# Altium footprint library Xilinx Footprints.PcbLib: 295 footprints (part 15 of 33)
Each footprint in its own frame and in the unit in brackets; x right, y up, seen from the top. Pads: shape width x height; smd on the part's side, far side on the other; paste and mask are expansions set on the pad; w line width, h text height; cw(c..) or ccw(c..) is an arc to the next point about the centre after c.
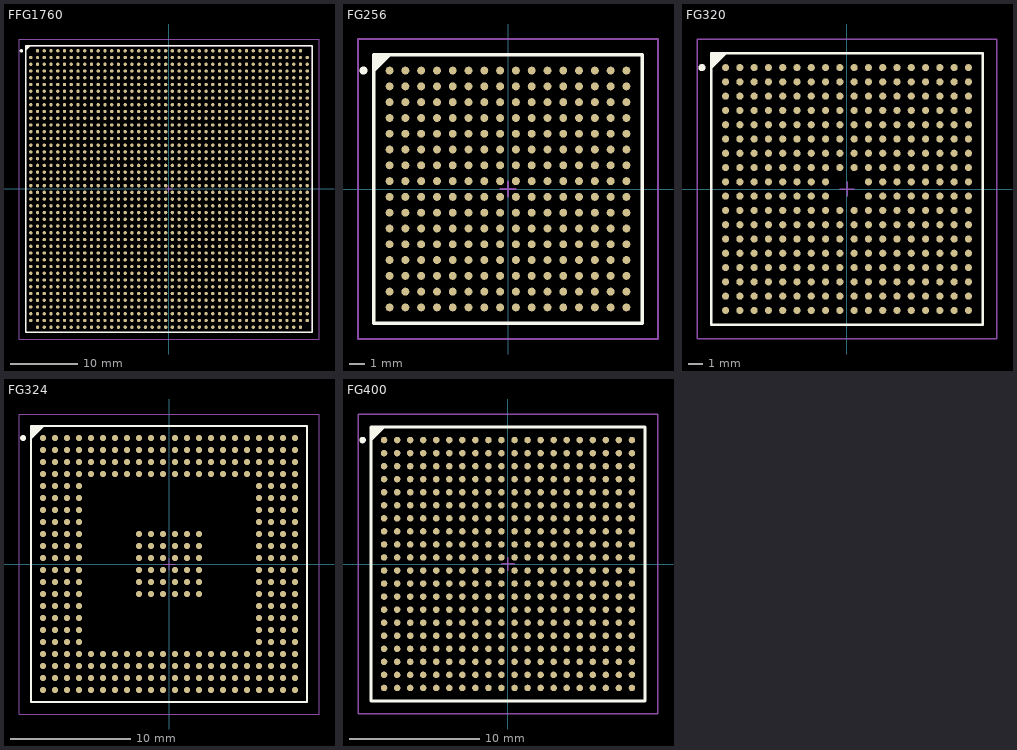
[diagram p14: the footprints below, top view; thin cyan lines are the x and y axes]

## FFG1760 [mm] "1760-Ball Flip Chip Fine Pitch Ball Grid Array (FFG1760) - Pb-Free"
height 3.5
pads (1760):
  round 0.5 smd: A2(-19.5,20.5) A3(-18.5,20.5) A4(-17.5,20.5) A5(-16.5,20.5) A6(-15.5,20.5) A7(-14.5,20.5) A8(-13.5,20.5) A9(-12.5,20.5) A10(-11.5,20.5) A11(-10.5,20.5) A12(-9.5,20.5) A13(-8.5,20.5) A14(-7.5,20.5) A15(-6.5,20.5) A16(-5.5,20.5) A17(-4.5,20.5) A18(-3.5,20.5) A19(-2.5,20.5) A20(-1.5,20.5) A21(-0.5,20.5) A22(0.5,20.5) A23(1.5,20.5) A24(2.5,20.5) A25(3.5,20.5) A26(4.5,20.5) A27(5.5,20.5) A28(6.5,20.5) A29(7.5,20.5) A30(8.5,20.5) A31(9.5,20.5) A32(10.5,20.5) A33(11.5,20.5) A34(12.5,20.5) A35(13.5,20.5) A36(14.5,20.5) A37(15.5,20.5) A38(16.5,20.5) A39(17.5,20.5) A40(18.5,20.5) A41(19.5,20.5) AA1(-20.5,0.5) AA2(-19.5,0.5) AA3(-18.5,0.5) AA4(-17.5,0.5) AA5(-16.5,0.5) AA6(-15.5,0.5) AA7(-14.5,0.5) AA8(-13.5,0.5) AA9(-12.5,0.5) AA10(-11.5,0.5) AA11(-10.5,0.5) AA12(-9.5,0.5) AA13(-8.5,0.5) AA14(-7.5,0.5) AA15(-6.5,0.5) AA16(-5.5,0.5) AA17(-4.5,0.5) AA18(-3.5,0.5) AA19(-2.5,0.5) AA20(-1.5,0.5) AA21(-0.5,0.5) AA22(0.5,0.5) AA23(1.5,0.5) AA24(2.5,0.5) AA25(3.5,0.5) AA26(4.5,0.5) AA27(5.5,0.5) AA28(6.5,0.5) AA29(7.5,0.5) AA30(8.5,0.5) AA31(9.5,0.5) AA32(10.5,0.5) AA33(11.5,0.5) AA34(12.5,0.5) AA35(13.5,0.5) AA36(14.5,0.5) AA37(15.5,0.5) AA38(16.5,0.5) AA39(17.5,0.5) AA40(18.5,0.5) AA41(19.5,0.5) AA42(20.5,0.5) AB1(-20.5,-0.5) AB2(-19.5,-0.5) AB3(-18.5,-0.5) AB4(-17.5,-0.5) AB5(-16.5,-0.5) AB6(-15.5,-0.5) AB7(-14.5,-0.5) AB8(-13.5,-0.5) AB9(-12.5,-0.5) AB10(-11.5,-0.5) AB11(-10.5,-0.5) AB12(-9.5,-0.5) AB13(-8.5,-0.5) AB14(-7.5,-0.5) AB15(-6.5,-0.5) AB16(-5.5,-0.5) AB17(-4.5,-0.5) AB18(-3.5,-0.5) AB19(-2.5,-0.5) AB20(-1.5,-0.5) AB21(-0.5,-0.5) AB22(0.5,-0.5) AB23(1.5,-0.5) AB24(2.5,-0.5) AB25(3.5,-0.5) AB26(4.5,-0.5) AB27(5.5,-0.5) AB28(6.5,-0.5) AB29(7.5,-0.5) AB30(8.5,-0.5) AB31(9.5,-0.5) AB32(10.5,-0.5) AB33(11.5,-0.5) AB34(12.5,-0.5) AB35(13.5,-0.5) AB36(14.5,-0.5) AB37(15.5,-0.5) AB38(16.5,-0.5) AB39(17.5,-0.5) AB40(18.5,-0.5) AB41(19.5,-0.5) AB42(20.5,-0.5) AC1(-20.5,-1.5) AC2(-19.5,-1.5) AC3(-18.5,-1.5) AC4(-17.5,-1.5) AC5(-16.5,-1.5) AC6(-15.5,-1.5) AC7(-14.5,-1.5) AC8(-13.5,-1.5) AC9(-12.5,-1.5) AC10(-11.5,-1.5) AC11(-10.5,-1.5) AC12(-9.5,-1.5) AC13(-8.5,-1.5) AC14(-7.5,-1.5) AC15(-6.5,-1.5) AC16(-5.5,-1.5) AC17(-4.5,-1.5) AC18(-3.5,-1.5) AC19(-2.5,-1.5) AC20(-1.5,-1.5) AC21(-0.5,-1.5) AC22(0.5,-1.5) AC23(1.5,-1.5) AC24(2.5,-1.5) AC25(3.5,-1.5) AC26(4.5,-1.5) AC27(5.5,-1.5) AC28(6.5,-1.5) AC29(7.5,-1.5) AC30(8.5,-1.5) AC31(9.5,-1.5) AC32(10.5,-1.5) AC33(11.5,-1.5) AC34(12.5,-1.5) AC35(13.5,-1.5) AC36(14.5,-1.5) AC37(15.5,-1.5) AC38(16.5,-1.5) AC39(17.5,-1.5) AC40(18.5,-1.5) AC41(19.5,-1.5) AC42(20.5,-1.5) AD1(-20.5,-2.5) AD2(-19.5,-2.5) AD3(-18.5,-2.5) AD4(-17.5,-2.5) AD5(-16.5,-2.5) AD6(-15.5,-2.5) AD7(-14.5,-2.5) AD8(-13.5,-2.5) AD9(-12.5,-2.5) AD10(-11.5,-2.5) AD11(-10.5,-2.5) AD12(-9.5,-2.5) AD13(-8.5,-2.5) AD14(-7.5,-2.5) AD15(-6.5,-2.5) AD16(-5.5,-2.5) AD17(-4.5,-2.5) AD18(-3.5,-2.5) AD19(-2.5,-2.5) AD20(-1.5,-2.5) AD21(-0.5,-2.5) AD22(0.5,-2.5) AD23(1.5,-2.5) AD24(2.5,-2.5) AD25(3.5,-2.5) AD26(4.5,-2.5) AD27(5.5,-2.5) AD28(6.5,-2.5) AD29(7.5,-2.5) AD30(8.5,-2.5) AD31(9.5,-2.5) AD32(10.5,-2.5) AD33(11.5,-2.5) AD34(12.5,-2.5) AD35(13.5,-2.5) AD36(14.5,-2.5) AD37(15.5,-2.5) AD38(16.5,-2.5) AD39(17.5,-2.5) AD40(18.5,-2.5) AD41(19.5,-2.5) AD42(20.5,-2.5) AE1(-20.5,-3.5) AE2(-19.5,-3.5) AE3(-18.5,-3.5) AE4(-17.5,-3.5) AE5(-16.5,-3.5) AE6(-15.5,-3.5) AE7(-14.5,-3.5) AE8(-13.5,-3.5) AE9(-12.5,-3.5) AE10(-11.5,-3.5) AE11(-10.5,-3.5) AE12(-9.5,-3.5) AE13(-8.5,-3.5) AE14(-7.5,-3.5) AE15(-6.5,-3.5) AE16(-5.5,-3.5) AE17(-4.5,-3.5) AE18(-3.5,-3.5) AE19(-2.5,-3.5) AE20(-1.5,-3.5) AE21(-0.5,-3.5) AE22(0.5,-3.5) AE23(1.5,-3.5) AE24(2.5,-3.5) AE25(3.5,-3.5) AE26(4.5,-3.5) AE27(5.5,-3.5) AE28(6.5,-3.5) AE29(7.5,-3.5) AE30(8.5,-3.5) AE31(9.5,-3.5) AE32(10.5,-3.5) AE33(11.5,-3.5) AE34(12.5,-3.5) AE35(13.5,-3.5) AE36(14.5,-3.5) AE37(15.5,-3.5) AE38(16.5,-3.5) AE39(17.5,-3.5) AE40(18.5,-3.5) AE41(19.5,-3.5) AE42(20.5,-3.5) AF1(-20.5,-4.5) AF2(-19.5,-4.5) AF3(-18.5,-4.5) AF4(-17.5,-4.5) AF5(-16.5,-4.5) AF6(-15.5,-4.5) AF7(-14.5,-4.5) AF8(-13.5,-4.5) AF9(-12.5,-4.5) AF10(-11.5,-4.5) AF11(-10.5,-4.5) AF12(-9.5,-4.5) AF13(-8.5,-4.5) AF14(-7.5,-4.5) AF15(-6.5,-4.5) AF16(-5.5,-4.5) AF17(-4.5,-4.5) AF18(-3.5,-4.5) AF19(-2.5,-4.5) AF20(-1.5,-4.5) AF21(-0.5,-4.5) AF22(0.5,-4.5) AF23(1.5,-4.5) AF24(2.5,-4.5) AF25(3.5,-4.5) AF26(4.5,-4.5) AF27(5.5,-4.5) AF28(6.5,-4.5) AF29(7.5,-4.5) AF30(8.5,-4.5) AF31(9.5,-4.5) AF32(10.5,-4.5) AF33(11.5,-4.5) AF34(12.5,-4.5) AF35(13.5,-4.5) AF36(14.5,-4.5) AF37(15.5,-4.5) AF38(16.5,-4.5) AF39(17.5,-4.5) AF40(18.5,-4.5) AF41(19.5,-4.5) AF42(20.5,-4.5) AG1(-20.5,-5.5) AG2(-19.5,-5.5) AG3(-18.5,-5.5) AG4(-17.5,-5.5) AG5(-16.5,-5.5) AG6(-15.5,-5.5) AG7(-14.5,-5.5) AG8(-13.5,-5.5) AG9(-12.5,-5.5) AG10(-11.5,-5.5) AG11(-10.5,-5.5) AG12(-9.5,-5.5) AG13(-8.5,-5.5) AG14(-7.5,-5.5) AG15(-6.5,-5.5) AG16(-5.5,-5.5) AG17(-4.5,-5.5) AG18(-3.5,-5.5) AG19(-2.5,-5.5) AG20(-1.5,-5.5) AG21(-0.5,-5.5) AG22(0.5,-5.5) AG23(1.5,-5.5) AG24(2.5,-5.5) AG25(3.5,-5.5) AG26(4.5,-5.5) AG27(5.5,-5.5) AG28(6.5,-5.5) AG29(7.5,-5.5) AG30(8.5,-5.5) AG31(9.5,-5.5) AG32(10.5,-5.5) AG33(11.5,-5.5) AG34(12.5,-5.5) AG35(13.5,-5.5) AG36(14.5,-5.5) AG37(15.5,-5.5) AG38(16.5,-5.5) AG39(17.5,-5.5) AG40(18.5,-5.5) AG41(19.5,-5.5) AG42(20.5,-5.5) AH1(-20.5,-6.5) AH2(-19.5,-6.5) AH3(-18.5,-6.5) AH4(-17.5,-6.5) AH5(-16.5,-6.5) AH6(-15.5,-6.5) AH7(-14.5,-6.5) AH8(-13.5,-6.5) AH9(-12.5,-6.5) AH10(-11.5,-6.5) AH11(-10.5,-6.5) AH12(-9.5,-6.5) AH13(-8.5,-6.5) AH14(-7.5,-6.5) AH15(-6.5,-6.5) AH16(-5.5,-6.5) AH17(-4.5,-6.5) AH18(-3.5,-6.5) AH19(-2.5,-6.5) AH20(-1.5,-6.5) AH21(-0.5,-6.5) AH22(0.5,-6.5) AH23(1.5,-6.5) AH24(2.5,-6.5) AH25(3.5,-6.5) AH26(4.5,-6.5) AH27(5.5,-6.5) AH28(6.5,-6.5) AH29(7.5,-6.5) AH30(8.5,-6.5) AH31(9.5,-6.5) AH32(10.5,-6.5) AH33(11.5,-6.5) AH34(12.5,-6.5) AH35(13.5,-6.5) AH36(14.5,-6.5) AH37(15.5,-6.5) AH38(16.5,-6.5) AH39(17.5,-6.5) AH40(18.5,-6.5) AH41(19.5,-6.5) AH42(20.5,-6.5) AJ1(-20.5,-7.5) AJ2(-19.5,-7.5) AJ3(-18.5,-7.5) AJ4(-17.5,-7.5) AJ5(-16.5,-7.5) AJ6(-15.5,-7.5) AJ7(-14.5,-7.5) AJ8(-13.5,-7.5) AJ9(-12.5,-7.5) AJ10(-11.5,-7.5) AJ11(-10.5,-7.5) AJ12(-9.5,-7.5) AJ13(-8.5,-7.5) AJ14(-7.5,-7.5) AJ15(-6.5,-7.5) AJ16(-5.5,-7.5) AJ17(-4.5,-7.5) AJ18(-3.5,-7.5) AJ19(-2.5,-7.5) AJ20(-1.5,-7.5) AJ21(-0.5,-7.5) AJ22(0.5,-7.5) AJ23(1.5,-7.5) AJ24(2.5,-7.5) AJ25(3.5,-7.5) AJ26(4.5,-7.5) AJ27(5.5,-7.5) AJ28(6.5,-7.5) AJ29(7.5,-7.5) AJ30(8.5,-7.5) AJ31(9.5,-7.5) AJ32(10.5,-7.5) AJ33(11.5,-7.5) AJ34(12.5,-7.5) AJ35(13.5,-7.5) AJ36(14.5,-7.5) AJ37(15.5,-7.5) AJ38(16.5,-7.5) AJ39(17.5,-7.5) AJ40(18.5,-7.5) AJ41(19.5,-7.5) AJ42(20.5,-7.5) AK1(-20.5,-8.5) AK2(-19.5,-8.5) AK3(-18.5,-8.5) AK4(-17.5,-8.5) AK5(-16.5,-8.5) AK6(-15.5,-8.5) AK7(-14.5,-8.5) AK8(-13.5,-8.5) AK9(-12.5,-8.5) AK10(-11.5,-8.5) AK11(-10.5,-8.5) AK12(-9.5,-8.5) AK13(-8.5,-8.5) AK14(-7.5,-8.5) AK15(-6.5,-8.5) AK16(-5.5,-8.5) AK17(-4.5,-8.5) AK18(-3.5,-8.5) AK19(-2.5,-8.5) AK20(-1.5,-8.5) AK21(-0.5,-8.5) AK22(0.5,-8.5) AK23(1.5,-8.5) AK24(2.5,-8.5) AK25(3.5,-8.5) AK26(4.5,-8.5) AK27(5.5,-8.5) AK28(6.5,-8.5) AK29(7.5,-8.5) AK30(8.5,-8.5) AK31(9.5,-8.5) AK32(10.5,-8.5) AK33(11.5,-8.5) AK34(12.5,-8.5) AK35(13.5,-8.5) AK36(14.5,-8.5) AK37(15.5,-8.5) AK38(16.5,-8.5) AK39(17.5,-8.5) AK40(18.5,-8.5) AK41(19.5,-8.5) AK42(20.5,-8.5) AL1(-20.5,-9.5) AL2(-19.5,-9.5) AL3(-18.5,-9.5) AL4(-17.5,-9.5) AL5(-16.5,-9.5) AL6(-15.5,-9.5) AL7(-14.5,-9.5) AL8(-13.5,-9.5) AL9(-12.5,-9.5) AL10(-11.5,-9.5) AL11(-10.5,-9.5) AL12(-9.5,-9.5) AL13(-8.5,-9.5) AL14(-7.5,-9.5) AL15(-6.5,-9.5) AL16(-5.5,-9.5) AL17(-4.5,-9.5) AL18(-3.5,-9.5) AL19(-2.5,-9.5) AL20(-1.5,-9.5) AL21(-0.5,-9.5) AL22(0.5,-9.5) AL23(1.5,-9.5) AL24(2.5,-9.5) AL25(3.5,-9.5) AL26(4.5,-9.5) AL27(5.5,-9.5) AL28(6.5,-9.5) AL29(7.5,-9.5) AL30(8.5,-9.5) AL31(9.5,-9.5) AL32(10.5,-9.5) AL33(11.5,-9.5) AL34(12.5,-9.5) AL35(13.5,-9.5) AL36(14.5,-9.5) AL37(15.5,-9.5) AL38(16.5,-9.5) AL39(17.5,-9.5) AL40(18.5,-9.5) AL41(19.5,-9.5) AL42(20.5,-9.5) AM1(-20.5,-10.5) AM2(-19.5,-10.5) AM3(-18.5,-10.5) AM4(-17.5,-10.5) AM5(-16.5,-10.5) AM6(-15.5,-10.5) AM7(-14.5,-10.5) AM8(-13.5,-10.5) AM9(-12.5,-10.5) AM10(-11.5,-10.5) AM11(-10.5,-10.5) AM12(-9.5,-10.5) AM13(-8.5,-10.5) AM14(-7.5,-10.5) AM15(-6.5,-10.5) AM16(-5.5,-10.5) AM17(-4.5,-10.5) AM18(-3.5,-10.5) AM19(-2.5,-10.5) AM20(-1.5,-10.5) AM21(-0.5,-10.5) AM22(0.5,-10.5) AM23(1.5,-10.5) AM24(2.5,-10.5) AM25(3.5,-10.5) AM26(4.5,-10.5) AM27(5.5,-10.5) AM28(6.5,-10.5) AM29(7.5,-10.5) AM30(8.5,-10.5) AM31(9.5,-10.5) AM32(10.5,-10.5) AM33(11.5,-10.5) AM34(12.5,-10.5) AM35(13.5,-10.5) AM36(14.5,-10.5) AM37(15.5,-10.5) AM38(16.5,-10.5) AM39(17.5,-10.5) AM40(18.5,-10.5) AM41(19.5,-10.5) AM42(20.5,-10.5) AN1(-20.5,-11.5) AN2(-19.5,-11.5) AN3(-18.5,-11.5) AN4(-17.5,-11.5) AN5(-16.5,-11.5) AN6(-15.5,-11.5) AN7(-14.5,-11.5) AN8(-13.5,-11.5) AN9(-12.5,-11.5) AN10(-11.5,-11.5) AN11(-10.5,-11.5) AN12(-9.5,-11.5) AN13(-8.5,-11.5) AN14(-7.5,-11.5) AN15(-6.5,-11.5) AN16(-5.5,-11.5) AN17(-4.5,-11.5) AN18(-3.5,-11.5) AN19(-2.5,-11.5) AN20(-1.5,-11.5) AN21(-0.5,-11.5) AN22(0.5,-11.5) AN23(1.5,-11.5) AN24(2.5,-11.5) AN25(3.5,-11.5) AN26(4.5,-11.5) AN27(5.5,-11.5) AN28(6.5,-11.5) AN29(7.5,-11.5) AN30(8.5,-11.5) AN31(9.5,-11.5) AN32(10.5,-11.5) AN33(11.5,-11.5) AN34(12.5,-11.5) AN35(13.5,-11.5) AN36(14.5,-11.5) AN37(15.5,-11.5) AN38(16.5,-11.5) AN39(17.5,-11.5) AN40(18.5,-11.5) AN41(19.5,-11.5) AN42(20.5,-11.5) AP1(-20.5,-12.5) AP2(-19.5,-12.5) AP3(-18.5,-12.5) AP4(-17.5,-12.5) AP5(-16.5,-12.5) AP6(-15.5,-12.5) AP7(-14.5,-12.5) AP8(-13.5,-12.5) AP9(-12.5,-12.5) AP10(-11.5,-12.5) AP11(-10.5,-12.5) AP12(-9.5,-12.5) AP13(-8.5,-12.5) AP14(-7.5,-12.5) AP15(-6.5,-12.5) AP16(-5.5,-12.5) AP17(-4.5,-12.5) AP18(-3.5,-12.5) AP19(-2.5,-12.5) AP20(-1.5,-12.5) AP21(-0.5,-12.5) AP22(0.5,-12.5) AP23(1.5,-12.5) AP24(2.5,-12.5) AP25(3.5,-12.5) AP26(4.5,-12.5) AP27(5.5,-12.5) AP28(6.5,-12.5) AP29(7.5,-12.5) AP30(8.5,-12.5) AP31(9.5,-12.5) AP32(10.5,-12.5) AP33(11.5,-12.5) AP34(12.5,-12.5) AP35(13.5,-12.5) AP36(14.5,-12.5) AP37(15.5,-12.5) AP38(16.5,-12.5) AP39(17.5,-12.5) AP40(18.5,-12.5) AP41(19.5,-12.5) AP42(20.5,-12.5) AR1(-20.5,-13.5) AR2(-19.5,-13.5) AR3(-18.5,-13.5) AR4(-17.5,-13.5) AR5(-16.5,-13.5) AR6(-15.5,-13.5) AR7(-14.5,-13.5) AR8(-13.5,-13.5) AR9(-12.5,-13.5) AR10(-11.5,-13.5) AR11(-10.5,-13.5) AR12(-9.5,-13.5) AR13(-8.5,-13.5) AR14(-7.5,-13.5) AR15(-6.5,-13.5) AR16(-5.5,-13.5) AR17(-4.5,-13.5) AR18(-3.5,-13.5) AR19(-2.5,-13.5) AR20(-1.5,-13.5) AR21(-0.5,-13.5) AR22(0.5,-13.5) AR23(1.5,-13.5) AR24(2.5,-13.5) AR25(3.5,-13.5) AR26(4.5,-13.5) AR27(5.5,-13.5) AR28(6.5,-13.5) AR29(7.5,-13.5) AR30(8.5,-13.5) AR31(9.5,-13.5) AR32(10.5,-13.5) AR33(11.5,-13.5) AR34(12.5,-13.5) AR35(13.5,-13.5) AR36(14.5,-13.5) AR37(15.5,-13.5) AR38(16.5,-13.5) AR39(17.5,-13.5) AR40(18.5,-13.5) AR41(19.5,-13.5) AR42(20.5,-13.5) AT1(-20.5,-14.5) AT2(-19.5,-14.5) AT3(-18.5,-14.5) AT4(-17.5,-14.5) AT5(-16.5,-14.5) AT6(-15.5,-14.5) AT7(-14.5,-14.5) AT8(-13.5,-14.5) AT9(-12.5,-14.5) AT10(-11.5,-14.5) AT11(-10.5,-14.5) AT12(-9.5,-14.5) AT13(-8.5,-14.5) AT14(-7.5,-14.5) AT15(-6.5,-14.5) AT16(-5.5,-14.5) AT17(-4.5,-14.5) AT18(-3.5,-14.5) AT19(-2.5,-14.5) AT20(-1.5,-14.5) AT21(-0.5,-14.5) AT22(0.5,-14.5) AT23(1.5,-14.5) AT24(2.5,-14.5) AT25(3.5,-14.5) AT26(4.5,-14.5) AT27(5.5,-14.5) AT28(6.5,-14.5) AT29(7.5,-14.5) AT30(8.5,-14.5) AT31(9.5,-14.5) AT32(10.5,-14.5) AT33(11.5,-14.5) AT34(12.5,-14.5) AT35(13.5,-14.5) AT36(14.5,-14.5) AT37(15.5,-14.5) AT38(16.5,-14.5) AT39(17.5,-14.5) AT40(18.5,-14.5) AT41(19.5,-14.5) AT42(20.5,-14.5) AU1(-20.5,-15.5) AU2(-19.5,-15.5) AU3(-18.5,-15.5) AU4(-17.5,-15.5) AU5(-16.5,-15.5) AU6(-15.5,-15.5) AU7(-14.5,-15.5) AU8(-13.5,-15.5) AU9(-12.5,-15.5) AU10(-11.5,-15.5) AU11(-10.5,-15.5) AU12(-9.5,-15.5) AU13(-8.5,-15.5) AU14(-7.5,-15.5) AU15(-6.5,-15.5) AU16(-5.5,-15.5) AU17(-4.5,-15.5) AU18(-3.5,-15.5) AU19(-2.5,-15.5) AU20(-1.5,-15.5) AU21(-0.5,-15.5) AU22(0.5,-15.5) AU23(1.5,-15.5) AU24(2.5,-15.5) AU25(3.5,-15.5) AU26(4.5,-15.5) AU27(5.5,-15.5) AU28(6.5,-15.5) AU29(7.5,-15.5) AU30(8.5,-15.5) AU31(9.5,-15.5) AU32(10.5,-15.5) AU33(11.5,-15.5) AU34(12.5,-15.5) AU35(13.5,-15.5) AU36(14.5,-15.5) AU37(15.5,-15.5) AU38(16.5,-15.5) AU39(17.5,-15.5) AU40(18.5,-15.5) AU41(19.5,-15.5) AU42(20.5,-15.5) AV1(-20.5,-16.5) AV2(-19.5,-16.5) AV3(-18.5,-16.5) AV4(-17.5,-16.5) AV5(-16.5,-16.5) AV6(-15.5,-16.5) AV7(-14.5,-16.5) AV8(-13.5,-16.5) AV9(-12.5,-16.5) AV10(-11.5,-16.5) AV11(-10.5,-16.5) AV12(-9.5,-16.5) AV13(-8.5,-16.5) AV14(-7.5,-16.5) AV15(-6.5,-16.5) AV16(-5.5,-16.5) AV17(-4.5,-16.5) AV18(-3.5,-16.5) AV19(-2.5,-16.5) AV20(-1.5,-16.5) AV21(-0.5,-16.5) AV22(0.5,-16.5) AV23(1.5,-16.5) AV24(2.5,-16.5) AV25(3.5,-16.5) AV26(4.5,-16.5) AV27(5.5,-16.5) AV28(6.5,-16.5) AV29(7.5,-16.5) AV30(8.5,-16.5) AV31(9.5,-16.5) AV32(10.5,-16.5) AV33(11.5,-16.5) AV34(12.5,-16.5) AV35(13.5,-16.5) AV36(14.5,-16.5) AV37(15.5,-16.5) AV38(16.5,-16.5) AV39(17.5,-16.5) AV40(18.5,-16.5) AV41(19.5,-16.5) AV42(20.5,-16.5) AW1(-20.5,-17.5) AW2(-19.5,-17.5) AW3(-18.5,-17.5) AW4(-17.5,-17.5) AW5(-16.5,-17.5) AW6(-15.5,-17.5) AW7(-14.5,-17.5) AW8(-13.5,-17.5) AW9(-12.5,-17.5) AW10(-11.5,-17.5) AW11(-10.5,-17.5) AW12(-9.5,-17.5) AW13(-8.5,-17.5) AW14(-7.5,-17.5) AW15(-6.5,-17.5) AW16(-5.5,-17.5) AW17(-4.5,-17.5) AW18(-3.5,-17.5) AW19(-2.5,-17.5) AW20(-1.5,-17.5) AW21(-0.5,-17.5) AW22(0.5,-17.5) AW23(1.5,-17.5) AW24(2.5,-17.5) AW25(3.5,-17.5) AW26(4.5,-17.5) AW27(5.5,-17.5) AW28(6.5,-17.5) AW29(7.5,-17.5) AW30(8.5,-17.5) AW31(9.5,-17.5) AW32(10.5,-17.5) AW33(11.5,-17.5) AW34(12.5,-17.5) AW35(13.5,-17.5) AW36(14.5,-17.5) AW37(15.5,-17.5) AW38(16.5,-17.5) AW39(17.5,-17.5) AW40(18.5,-17.5) AW41(19.5,-17.5) AW42(20.5,-17.5) AY1(-20.5,-18.5) AY2(-19.5,-18.5) AY3(-18.5,-18.5) AY4(-17.5,-18.5) AY5(-16.5,-18.5) AY6(-15.5,-18.5) AY7(-14.5,-18.5) AY8(-13.5,-18.5) AY9(-12.5,-18.5) AY10(-11.5,-18.5) AY11(-10.5,-18.5) AY12(-9.5,-18.5) AY13(-8.5,-18.5) AY14(-7.5,-18.5) AY15(-6.5,-18.5) AY16(-5.5,-18.5) AY17(-4.5,-18.5) AY18(-3.5,-18.5) AY19(-2.5,-18.5) AY20(-1.5,-18.5) AY21(-0.5,-18.5) AY22(0.5,-18.5) AY23(1.5,-18.5) AY24(2.5,-18.5) AY25(3.5,-18.5) AY26(4.5,-18.5) AY27(5.5,-18.5) AY28(6.5,-18.5) AY29(7.5,-18.5) AY30(8.5,-18.5) AY31(9.5,-18.5) AY32(10.5,-18.5) AY33(11.5,-18.5) AY34(12.5,-18.5) AY35(13.5,-18.5) AY36(14.5,-18.5) AY37(15.5,-18.5) AY38(16.5,-18.5) AY39(17.5,-18.5) AY40(18.5,-18.5) AY41(19.5,-18.5) AY42(20.5,-18.5) B1(-20.5,19.5) B2(-19.5,19.5) B3(-18.5,19.5) B4(-17.5,19.5) B5(-16.5,19.5) B6(-15.5,19.5) B7(-14.5,19.5) B8(-13.5,19.5) B9(-12.5,19.5) B10(-11.5,19.5) B11(-10.5,19.5) B12(-9.5,19.5) B13(-8.5,19.5) B14(-7.5,19.5) B15(-6.5,19.5) B16(-5.5,19.5) B17(-4.5,19.5) B18(-3.5,19.5) B19(-2.5,19.5) B20(-1.5,19.5) B21(-0.5,19.5) B22(0.5,19.5) B23(1.5,19.5) B24(2.5,19.5) B25(3.5,19.5) B26(4.5,19.5) B27(5.5,19.5) B28(6.5,19.5) B29(7.5,19.5) B30(8.5,19.5) B31(9.5,19.5) B32(10.5,19.5) B33(11.5,19.5) B34(12.5,19.5) B35(13.5,19.5) B36(14.5,19.5) B37(15.5,19.5) B38(16.5,19.5) B39(17.5,19.5) B40(18.5,19.5) B41(19.5,19.5) B42(20.5,19.5) BA1(-20.5,-19.5) BA2(-19.5,-19.5) BA3(-18.5,-19.5) BA4(-17.5,-19.5) BA5(-16.5,-19.5) BA6(-15.5,-19.5) BA7(-14.5,-19.5) BA8(-13.5,-19.5) BA9(-12.5,-19.5) BA10(-11.5,-19.5) BA11(-10.5,-19.5) BA12(-9.5,-19.5) BA13(-8.5,-19.5) BA14(-7.5,-19.5) BA15(-6.5,-19.5) BA16(-5.5,-19.5) BA17(-4.5,-19.5) BA18(-3.5,-19.5) BA19(-2.5,-19.5) BA20(-1.5,-19.5) BA21(-0.5,-19.5) BA22(0.5,-19.5) BA23(1.5,-19.5) BA24(2.5,-19.5) BA25(3.5,-19.5) BA26(4.5,-19.5) BA27(5.5,-19.5) BA28(6.5,-19.5) BA29(7.5,-19.5) BA30(8.5,-19.5) BA31(9.5,-19.5) BA32(10.5,-19.5) BA33(11.5,-19.5) BA34(12.5,-19.5) BA35(13.5,-19.5) BA36(14.5,-19.5) BA37(15.5,-19.5) BA38(16.5,-19.5) BA39(17.5,-19.5) BA40(18.5,-19.5) BA41(19.5,-19.5) BA42(20.5,-19.5) BB2(-19.5,-20.5) BB3(-18.5,-20.5) BB4(-17.5,-20.5) BB5(-16.5,-20.5) BB6(-15.5,-20.5) BB7(-14.5,-20.5) BB8(-13.5,-20.5) BB9(-12.5,-20.5) BB10(-11.5,-20.5) BB11(-10.5,-20.5) BB12(-9.5,-20.5) BB13(-8.5,-20.5) BB14(-7.5,-20.5) BB15(-6.5,-20.5) BB16(-5.5,-20.5) BB17(-4.5,-20.5) BB18(-3.5,-20.5) BB19(-2.5,-20.5) BB20(-1.5,-20.5) BB21(-0.5,-20.5) BB22(0.5,-20.5) BB23(1.5,-20.5) BB24(2.5,-20.5) BB25(3.5,-20.5) BB26(4.5,-20.5) BB27(5.5,-20.5) BB28(6.5,-20.5) BB29(7.5,-20.5) BB30(8.5,-20.5) BB31(9.5,-20.5) BB32(10.5,-20.5) BB33(11.5,-20.5) BB34(12.5,-20.5) BB35(13.5,-20.5) BB36(14.5,-20.5) BB37(15.5,-20.5) BB38(16.5,-20.5) BB39(17.5,-20.5) BB40(18.5,-20.5) BB41(19.5,-20.5) C1(-20.5,18.5) C2(-19.5,18.5) C3(-18.5,18.5) C4(-17.5,18.5) C5(-16.5,18.5) C6(-15.5,18.5) C7(-14.5,18.5) C8(-13.5,18.5) C9(-12.5,18.5) C10(-11.5,18.5) C11(-10.5,18.5) C12(-9.5,18.5) C13(-8.5,18.5) C14(-7.5,18.5) C15(-6.5,18.5) C16(-5.5,18.5) C17(-4.5,18.5) C18(-3.5,18.5) C19(-2.5,18.5) C20(-1.5,18.5) C21(-0.5,18.5) C22(0.5,18.5) C23(1.5,18.5) C24(2.5,18.5) C25(3.5,18.5) C26(4.5,18.5) C27(5.5,18.5) C28(6.5,18.5) C29(7.5,18.5) C30(8.5,18.5) C31(9.5,18.5) C32(10.5,18.5) C33(11.5,18.5) C34(12.5,18.5) C35(13.5,18.5) C36(14.5,18.5) C37(15.5,18.5) C38(16.5,18.5) C39(17.5,18.5) C40(18.5,18.5) C41(19.5,18.5) C42(20.5,18.5) D1(-20.5,17.5) D2(-19.5,17.5) D3(-18.5,17.5) D4(-17.5,17.5) D5(-16.5,17.5) D6(-15.5,17.5) D7(-14.5,17.5) D8(-13.5,17.5) D9(-12.5,17.5) D10(-11.5,17.5) D11(-10.5,17.5) D12(-9.5,17.5) D13(-8.5,17.5) D14(-7.5,17.5) D15(-6.5,17.5) D16(-5.5,17.5) D17(-4.5,17.5) D18(-3.5,17.5) D19(-2.5,17.5) D20(-1.5,17.5) D21(-0.5,17.5) D22(0.5,17.5) D23(1.5,17.5) D24(2.5,17.5) D25(3.5,17.5) D26(4.5,17.5) D27(5.5,17.5) D28(6.5,17.5) D29(7.5,17.5) D30(8.5,17.5) D31(9.5,17.5) D32(10.5,17.5) D33(11.5,17.5) D34(12.5,17.5) D35(13.5,17.5) D36(14.5,17.5) D37(15.5,17.5) D38(16.5,17.5) D39(17.5,17.5) D40(18.5,17.5) D41(19.5,17.5) D42(20.5,17.5) E1(-20.5,16.5) E2(-19.5,16.5) E3(-18.5,16.5) E4(-17.5,16.5) E5(-16.5,16.5) E6(-15.5,16.5) E7(-14.5,16.5) E8(-13.5,16.5) E9(-12.5,16.5) E10(-11.5,16.5) E11(-10.5,16.5) E12(-9.5,16.5) E13(-8.5,16.5) E14(-7.5,16.5) E15(-6.5,16.5) E16(-5.5,16.5) E17(-4.5,16.5) E18(-3.5,16.5) E19(-2.5,16.5) E20(-1.5,16.5) E21(-0.5,16.5) E22(0.5,16.5) E23(1.5,16.5) E24(2.5,16.5) E25(3.5,16.5) E26(4.5,16.5) E27(5.5,16.5) E28(6.5,16.5) E29(7.5,16.5) E30(8.5,16.5) E31(9.5,16.5) E32(10.5,16.5) E33(11.5,16.5) E34(12.5,16.5) E35(13.5,16.5) E36(14.5,16.5) E37(15.5,16.5) E38(16.5,16.5) E39(17.5,16.5) E40(18.5,16.5) E41(19.5,16.5) E42(20.5,16.5) F1(-20.5,15.5) F2(-19.5,15.5) F3(-18.5,15.5) F4(-17.5,15.5) F5(-16.5,15.5) F6(-15.5,15.5) F7(-14.5,15.5) F8(-13.5,15.5) F9(-12.5,15.5) F10(-11.5,15.5) F11(-10.5,15.5) F12(-9.5,15.5) F13(-8.5,15.5) F14(-7.5,15.5) F15(-6.5,15.5) F16(-5.5,15.5) F17(-4.5,15.5) F18(-3.5,15.5) F19(-2.5,15.5) F20(-1.5,15.5) F21(-0.5,15.5) F22(0.5,15.5) F23(1.5,15.5) F24(2.5,15.5) F25(3.5,15.5) F26(4.5,15.5) F27(5.5,15.5) F28(6.5,15.5) F29(7.5,15.5) F30(8.5,15.5) F31(9.5,15.5) F32(10.5,15.5) F33(11.5,15.5) F34(12.5,15.5) F35(13.5,15.5) F36(14.5,15.5) F37(15.5,15.5) F38(16.5,15.5) F39(17.5,15.5) F40(18.5,15.5) F41(19.5,15.5) F42(20.5,15.5) G1(-20.5,14.5) G2(-19.5,14.5) G3(-18.5,14.5) G4(-17.5,14.5) G5(-16.5,14.5) G6(-15.5,14.5) G7(-14.5,14.5) G8(-13.5,14.5) G9(-12.5,14.5) G10(-11.5,14.5) G11(-10.5,14.5) G12(-9.5,14.5) G13(-8.5,14.5) G14(-7.5,14.5) G15(-6.5,14.5) G16(-5.5,14.5) G17(-4.5,14.5) G18(-3.5,14.5) G19(-2.5,14.5) G20(-1.5,14.5) G21(-0.5,14.5) G22(0.5,14.5) G23(1.5,14.5) G24(2.5,14.5) G25(3.5,14.5) G26(4.5,14.5) G27(5.5,14.5) G28(6.5,14.5) G29(7.5,14.5) G30(8.5,14.5) G31(9.5,14.5) G32(10.5,14.5) G33(11.5,14.5) G34(12.5,14.5) G35(13.5,14.5) G36(14.5,14.5) G37(15.5,14.5) G38(16.5,14.5) G39(17.5,14.5) G40(18.5,14.5) G41(19.5,14.5) G42(20.5,14.5) H1(-20.5,13.5) H2(-19.5,13.5) H3(-18.5,13.5) H4(-17.5,13.5) H5(-16.5,13.5) H6(-15.5,13.5) H7(-14.5,13.5) H8(-13.5,13.5) H9(-12.5,13.5) H10(-11.5,13.5) H11(-10.5,13.5) H12(-9.5,13.5) H13(-8.5,13.5) H14(-7.5,13.5) H15(-6.5,13.5) H16(-5.5,13.5) H17(-4.5,13.5) H18(-3.5,13.5) H19(-2.5,13.5) H20(-1.5,13.5) H21(-0.5,13.5) H22(0.5,13.5) H23(1.5,13.5) H24(2.5,13.5) H25(3.5,13.5) H26(4.5,13.5) H27(5.5,13.5) H28(6.5,13.5) H29(7.5,13.5) H30(8.5,13.5) H31(9.5,13.5) H32(10.5,13.5) H33(11.5,13.5) H34(12.5,13.5) H35(13.5,13.5) H36(14.5,13.5) H37(15.5,13.5) H38(16.5,13.5) H39(17.5,13.5) H40(18.5,13.5) H41(19.5,13.5) H42(20.5,13.5) J1(-20.5,12.5) J2(-19.5,12.5) J3(-18.5,12.5) J4(-17.5,12.5) J5(-16.5,12.5) J6(-15.5,12.5) J7(-14.5,12.5) J8(-13.5,12.5) J9(-12.5,12.5) J10(-11.5,12.5) J11(-10.5,12.5) J12(-9.5,12.5) J13(-8.5,12.5) J14(-7.5,12.5) J15(-6.5,12.5) J16(-5.5,12.5) J17(-4.5,12.5) J18(-3.5,12.5) J19(-2.5,12.5) J20(-1.5,12.5) J21(-0.5,12.5) J22(0.5,12.5) J23(1.5,12.5) J24(2.5,12.5) J25(3.5,12.5) J26(4.5,12.5) J27(5.5,12.5) J28(6.5,12.5) J29(7.5,12.5) J30(8.5,12.5) J31(9.5,12.5) J32(10.5,12.5) J33(11.5,12.5) J34(12.5,12.5) J35(13.5,12.5) J36(14.5,12.5) J37(15.5,12.5) J38(16.5,12.5) J39(17.5,12.5) J40(18.5,12.5) J41(19.5,12.5) J42(20.5,12.5) K1(-20.5,11.5) K2(-19.5,11.5) K3(-18.5,11.5) K4(-17.5,11.5) K5(-16.5,11.5) K6(-15.5,11.5) K7(-14.5,11.5) K8(-13.5,11.5) K9(-12.5,11.5) K10(-11.5,11.5) K11(-10.5,11.5) K12(-9.5,11.5) K13(-8.5,11.5) K14(-7.5,11.5) K15(-6.5,11.5) K16(-5.5,11.5) K17(-4.5,11.5) K18(-3.5,11.5) K19(-2.5,11.5) K20(-1.5,11.5) K21(-0.5,11.5) K22(0.5,11.5) K23(1.5,11.5) K24(2.5,11.5) K25(3.5,11.5) K26(4.5,11.5) K27(5.5,11.5) K28(6.5,11.5) K29(7.5,11.5) K30(8.5,11.5) K31(9.5,11.5) K32(10.5,11.5) K33(11.5,11.5) K34(12.5,11.5) K35(13.5,11.5) K36(14.5,11.5) K37(15.5,11.5) K38(16.5,11.5) K39(17.5,11.5) K40(18.5,11.5) K41(19.5,11.5) K42(20.5,11.5) L1(-20.5,10.5) L2(-19.5,10.5) L3(-18.5,10.5) L4(-17.5,10.5) L5(-16.5,10.5) L6(-15.5,10.5) L7(-14.5,10.5) L8(-13.5,10.5) L9(-12.5,10.5) L10(-11.5,10.5) L11(-10.5,10.5) L12(-9.5,10.5) L13(-8.5,10.5) L14(-7.5,10.5) L15(-6.5,10.5) L16(-5.5,10.5) L17(-4.5,10.5) L18(-3.5,10.5) L19(-2.5,10.5) L20(-1.5,10.5) L21(-0.5,10.5) L22(0.5,10.5) L23(1.5,10.5) L24(2.5,10.5) L25(3.5,10.5) L26(4.5,10.5) L27(5.5,10.5) L28(6.5,10.5) L29(7.5,10.5) L30(8.5,10.5) L31(9.5,10.5) L32(10.5,10.5) L33(11.5,10.5) L34(12.5,10.5) L35(13.5,10.5) L36(14.5,10.5) L37(15.5,10.5) L38(16.5,10.5) L39(17.5,10.5) L40(18.5,10.5) L41(19.5,10.5) L42(20.5,10.5) M1(-20.5,9.5) M2(-19.5,9.5) M3(-18.5,9.5) M4(-17.5,9.5) M5(-16.5,9.5) M6(-15.5,9.5) M7(-14.5,9.5) M8(-13.5,9.5) M9(-12.5,9.5) M10(-11.5,9.5) M11(-10.5,9.5) M12(-9.5,9.5) M13(-8.5,9.5) M14(-7.5,9.5) M15(-6.5,9.5) M16(-5.5,9.5) M17(-4.5,9.5) M18(-3.5,9.5) M19(-2.5,9.5) M20(-1.5,9.5) M21(-0.5,9.5) M22(0.5,9.5) M23(1.5,9.5) M24(2.5,9.5) M25(3.5,9.5) M26(4.5,9.5) M27(5.5,9.5) M28(6.5,9.5) M29(7.5,9.5) M30(8.5,9.5) M31(9.5,9.5) M32(10.5,9.5) M33(11.5,9.5) M34(12.5,9.5) M35(13.5,9.5) M36(14.5,9.5) M37(15.5,9.5) M38(16.5,9.5) M39(17.5,9.5) M40(18.5,9.5) M41(19.5,9.5) M42(20.5,9.5) N1(-20.5,8.5) N2(-19.5,8.5) N3(-18.5,8.5) N4(-17.5,8.5) N5(-16.5,8.5) N6(-15.5,8.5) N7(-14.5,8.5) N8(-13.5,8.5) N9(-12.5,8.5) N10(-11.5,8.5) N11(-10.5,8.5) N12(-9.5,8.5) N13(-8.5,8.5) N14(-7.5,8.5) N15(-6.5,8.5) N16(-5.5,8.5) N17(-4.5,8.5) N18(-3.5,8.5) N19(-2.5,8.5) N20(-1.5,8.5) N21(-0.5,8.5) N22(0.5,8.5) N23(1.5,8.5) N24(2.5,8.5) N25(3.5,8.5) N26(4.5,8.5) N27(5.5,8.5) N28(6.5,8.5) N29(7.5,8.5) N30(8.5,8.5) N31(9.5,8.5) N32(10.5,8.5) N33(11.5,8.5) N34(12.5,8.5) N35(13.5,8.5) N36(14.5,8.5) N37(15.5,8.5) N38(16.5,8.5) N39(17.5,8.5) N40(18.5,8.5) N41(19.5,8.5) N42(20.5,8.5) P1(-20.5,7.5) P2(-19.5,7.5) P3(-18.5,7.5) P4(-17.5,7.5) P5(-16.5,7.5) P6(-15.5,7.5) P7(-14.5,7.5) P8(-13.5,7.5) P9(-12.5,7.5) P10(-11.5,7.5) P11(-10.5,7.5) P12(-9.5,7.5) P13(-8.5,7.5) P14(-7.5,7.5) P15(-6.5,7.5) P16(-5.5,7.5) P17(-4.5,7.5) P18(-3.5,7.5) P19(-2.5,7.5) P20(-1.5,7.5) P21(-0.5,7.5) P22(0.5,7.5) P23(1.5,7.5) P24(2.5,7.5) P25(3.5,7.5) P26(4.5,7.5) P27(5.5,7.5) P28(6.5,7.5) P29(7.5,7.5) P30(8.5,7.5) P31(9.5,7.5) P32(10.5,7.5) P33(11.5,7.5) P34(12.5,7.5) P35(13.5,7.5) P36(14.5,7.5) P37(15.5,7.5) P38(16.5,7.5) P39(17.5,7.5) P40(18.5,7.5) P41(19.5,7.5) P42(20.5,7.5) R1(-20.5,6.5) R2(-19.5,6.5) R3(-18.5,6.5) R4(-17.5,6.5) R5(-16.5,6.5) R6(-15.5,6.5) R7(-14.5,6.5) R8(-13.5,6.5) R9(-12.5,6.5) R10(-11.5,6.5) R11(-10.5,6.5) R12(-9.5,6.5) R13(-8.5,6.5) R14(-7.5,6.5) R15(-6.5,6.5) R16(-5.5,6.5) R17(-4.5,6.5) R18(-3.5,6.5) R19(-2.5,6.5) R20(-1.5,6.5) R21(-0.5,6.5) R22(0.5,6.5) R23(1.5,6.5) R24(2.5,6.5) R25(3.5,6.5) R26(4.5,6.5) R27(5.5,6.5) R28(6.5,6.5) R29(7.5,6.5) R30(8.5,6.5) R31(9.5,6.5) R32(10.5,6.5) R33(11.5,6.5) R34(12.5,6.5) R35(13.5,6.5) R36(14.5,6.5) R37(15.5,6.5) R38(16.5,6.5) R39(17.5,6.5) R40(18.5,6.5) R41(19.5,6.5) R42(20.5,6.5) T1(-20.5,5.5) T2(-19.5,5.5) T3(-18.5,5.5) T4(-17.5,5.5) T5(-16.5,5.5) T6(-15.5,5.5) T7(-14.5,5.5) T8(-13.5,5.5) T9(-12.5,5.5) T10(-11.5,5.5) T11(-10.5,5.5) T12(-9.5,5.5) T13(-8.5,5.5) T14(-7.5,5.5) T15(-6.5,5.5) T16(-5.5,5.5) T17(-4.5,5.5) T18(-3.5,5.5) T19(-2.5,5.5) T20(-1.5,5.5) T21(-0.5,5.5) T22(0.5,5.5) T23(1.5,5.5) T24(2.5,5.5) T25(3.5,5.5) T26(4.5,5.5) T27(5.5,5.5) T28(6.5,5.5) T29(7.5,5.5) T30(8.5,5.5) T31(9.5,5.5) T32(10.5,5.5) T33(11.5,5.5) T34(12.5,5.5) T35(13.5,5.5) T36(14.5,5.5) T37(15.5,5.5) T38(16.5,5.5) T39(17.5,5.5) T40(18.5,5.5) T41(19.5,5.5) T42(20.5,5.5) U1(-20.5,4.5) U2(-19.5,4.5) U3(-18.5,4.5) U4(-17.5,4.5) U5(-16.5,4.5) U6(-15.5,4.5) U7(-14.5,4.5) U8(-13.5,4.5) U9(-12.5,4.5) U10(-11.5,4.5) U11(-10.5,4.5) U12(-9.5,4.5) U13(-8.5,4.5) U14(-7.5,4.5) U15(-6.5,4.5) U16(-5.5,4.5) U17(-4.5,4.5) U18(-3.5,4.5) U19(-2.5,4.5) U20(-1.5,4.5) U21(-0.5,4.5) U22(0.5,4.5) U23(1.5,4.5) U24(2.5,4.5) U25(3.5,4.5) U26(4.5,4.5) U27(5.5,4.5) U28(6.5,4.5) U29(7.5,4.5) U30(8.5,4.5) U31(9.5,4.5) U32(10.5,4.5) U33(11.5,4.5) U34(12.5,4.5) U35(13.5,4.5) U36(14.5,4.5) U37(15.5,4.5) U38(16.5,4.5) U39(17.5,4.5) U40(18.5,4.5) U41(19.5,4.5) U42(20.5,4.5) V1(-20.5,3.5) V2(-19.5,3.5) V3(-18.5,3.5) V4(-17.5,3.5) V5(-16.5,3.5) V6(-15.5,3.5) V7(-14.5,3.5) V8(-13.5,3.5) V9(-12.5,3.5) V10(-11.5,3.5) V11(-10.5,3.5) V12(-9.5,3.5) V13(-8.5,3.5) V14(-7.5,3.5) V15(-6.5,3.5) V16(-5.5,3.5) V17(-4.5,3.5) V18(-3.5,3.5) V19(-2.5,3.5) V20(-1.5,3.5) V21(-0.5,3.5) V22(0.5,3.5) V23(1.5,3.5) V24(2.5,3.5) V25(3.5,3.5) V26(4.5,3.5) V27(5.5,3.5) V28(6.5,3.5) V29(7.5,3.5) V30(8.5,3.5) V31(9.5,3.5) V32(10.5,3.5) V33(11.5,3.5) V34(12.5,3.5) V35(13.5,3.5) V36(14.5,3.5) V37(15.5,3.5) V38(16.5,3.5) V39(17.5,3.5) V40(18.5,3.5) V41(19.5,3.5) V42(20.5,3.5) W1(-20.5,2.5) W2(-19.5,2.5) W3(-18.5,2.5) W4(-17.5,2.5) W5(-16.5,2.5) W6(-15.5,2.5) W7(-14.5,2.5) W8(-13.5,2.5) W9(-12.5,2.5) W10(-11.5,2.5) W11(-10.5,2.5) W12(-9.5,2.5) W13(-8.5,2.5) W14(-7.5,2.5) W15(-6.5,2.5) W16(-5.5,2.5) W17(-4.5,2.5) W18(-3.5,2.5) W19(-2.5,2.5) W20(-1.5,2.5) W21(-0.5,2.5) W22(0.5,2.5) W23(1.5,2.5) W24(2.5,2.5) W25(3.5,2.5) W26(4.5,2.5) W27(5.5,2.5) W28(6.5,2.5) W29(7.5,2.5) W30(8.5,2.5) W31(9.5,2.5) W32(10.5,2.5) W33(11.5,2.5) W34(12.5,2.5) W35(13.5,2.5) W36(14.5,2.5) W37(15.5,2.5) W38(16.5,2.5) W39(17.5,2.5) W40(18.5,2.5) W41(19.5,2.5) W42(20.5,2.5) Y1(-20.5,1.5) Y2(-19.5,1.5) Y3(-18.5,1.5) Y4(-17.5,1.5) Y5(-16.5,1.5) Y6(-15.5,1.5) Y7(-14.5,1.5) Y8(-13.5,1.5) Y9(-12.5,1.5) Y10(-11.5,1.5) Y11(-10.5,1.5) Y12(-9.5,1.5) Y13(-8.5,1.5) Y14(-7.5,1.5) Y15(-6.5,1.5) Y16(-5.5,1.5) Y17(-4.5,1.5) Y18(-3.5,1.5) Y19(-2.5,1.5) Y20(-1.5,1.5) Y21(-0.5,1.5) Y22(0.5,1.5) Y23(1.5,1.5) Y24(2.5,1.5) Y25(3.5,1.5) Y26(4.5,1.5) Y27(5.5,1.5) Y28(6.5,1.5) Y29(7.5,1.5) Y30(8.5,1.5) Y31(9.5,1.5) Y32(10.5,1.5) Y33(11.5,1.5) Y34(12.5,1.5) Y35(13.5,1.5) Y36(14.5,1.5) Y37(15.5,1.5) Y38(16.5,1.5) Y39(17.5,1.5) Y40(18.5,1.5) Y41(19.5,1.5) Y42(20.5,1.5)
Top Overlay:
  circle w0.25: c-21.9,20.5 r0.125
  region: -20.669,21.25 -21.25,20.669 -21.25,21.25
  lines w0.2: -21.25,20.669 -20.669,21.25 ; -21.25,-21.25 21.25,-21.25 21.25,21.25 -21.25,21.25 -21.25,-21.25
Mechanical 13:
  lines w0.1: -21.25,-21.25 21.25,-21.25 21.25,21.25 -21.25,21.25 -21.25,-21.25
Mechanical 15:
  lines w0.1: -0.5,0 0.5,0 ; 0,-0.5 0,0.5 ; -22.25,-22.25 22.25,-22.25 22.25,22.25 -22.25,22.25 -22.25,-22.25
3D body: height 3.5, standoff 0, extent -21.25,-21.25 21.25,21.25

## FG256 [mm] "256-Ball Fine Pitch Ball Grid Array (FG256)"
height 2
pads (256):
  round 0.5 smd: A1(-7.5,7.5) A2(-6.5,7.5) A3(-5.5,7.5) A4(-4.5,7.5) A5(-3.5,7.5) A6(-2.5,7.5) A7(-1.5,7.5) A8(-0.5,7.5) A9(0.5,7.5) A10(1.5,7.5) A11(2.5,7.5) A12(3.5,7.5) A13(4.5,7.5) A14(5.5,7.5) A15(6.5,7.5) A16(7.5,7.5) B1(-7.5,6.5) B2(-6.5,6.5) B3(-5.5,6.5) B4(-4.5,6.5) B5(-3.5,6.5) B6(-2.5,6.5) B7(-1.5,6.5) B8(-0.5,6.5) B9(0.5,6.5) B10(1.5,6.5) B11(2.5,6.5) B12(3.5,6.5) B13(4.5,6.5) B14(5.5,6.5) B15(6.5,6.5) B16(7.5,6.5) C1(-7.5,5.5) C2(-6.5,5.5) C3(-5.5,5.5) C4(-4.5,5.5) C5(-3.5,5.5) C6(-2.5,5.5) C7(-1.5,5.5) C8(-0.5,5.5) C9(0.5,5.5) C10(1.5,5.5) C11(2.5,5.5) C12(3.5,5.5) C13(4.5,5.5) C14(5.5,5.5) C15(6.5,5.5) C16(7.5,5.5) D1(-7.5,4.5) D2(-6.5,4.5) D3(-5.5,4.5) D4(-4.5,4.5) D5(-3.5,4.5) D6(-2.5,4.5) D7(-1.5,4.5) D8(-0.5,4.5) D9(0.5,4.5) D10(1.5,4.5) D11(2.5,4.5) D12(3.5,4.5) D13(4.5,4.5) D14(5.5,4.5) D15(6.5,4.5) D16(7.5,4.5) E1(-7.5,3.5) E2(-6.5,3.5) E3(-5.5,3.5) E4(-4.5,3.5) E5(-3.5,3.5) E6(-2.5,3.5) E7(-1.5,3.5) E8(-0.5,3.5) E9(0.5,3.5) E10(1.5,3.5) E11(2.5,3.5) E12(3.5,3.5) E13(4.5,3.5) E14(5.5,3.5) E15(6.5,3.5) E16(7.5,3.5) F1(-7.5,2.5) F2(-6.5,2.5) F3(-5.5,2.5) F4(-4.5,2.5) F5(-3.5,2.5) F6(-2.5,2.5) F7(-1.5,2.5) F8(-0.5,2.5) F9(0.5,2.5) F10(1.5,2.5) F11(2.5,2.5) F12(3.5,2.5) F13(4.5,2.5) F14(5.5,2.5) F15(6.5,2.5) F16(7.5,2.5) G1(-7.5,1.5) G2(-6.5,1.5) G3(-5.5,1.5) G4(-4.5,1.5) G5(-3.5,1.5) G6(-2.5,1.5) G7(-1.5,1.5) G8(-0.5,1.5) G9(0.5,1.5) G10(1.5,1.5) G11(2.5,1.5) G12(3.5,1.5) G13(4.5,1.5) G14(5.5,1.5) G15(6.5,1.5) G16(7.5,1.5) H1(-7.5,0.5) H2(-6.5,0.5) H3(-5.5,0.5) H4(-4.5,0.5) H5(-3.5,0.5) H6(-2.5,0.5) H7(-1.5,0.5) H8(-0.5,0.5) H9(0.5,0.5) H10(1.5,0.5) H11(2.5,0.5) H12(3.5,0.5) H13(4.5,0.5) H14(5.5,0.5) H15(6.5,0.5) H16(7.5,0.5) J1(-7.5,-0.5) J2(-6.5,-0.5) J3(-5.5,-0.5) J4(-4.5,-0.5) J5(-3.5,-0.5) J6(-2.5,-0.5) J7(-1.5,-0.5) J8(-0.5,-0.5) J9(0.5,-0.5) J10(1.5,-0.5) J11(2.5,-0.5) J12(3.5,-0.5) J13(4.5,-0.5) J14(5.5,-0.5) J15(6.5,-0.5) J16(7.5,-0.5) K1(-7.5,-1.5) K2(-6.5,-1.5) K3(-5.5,-1.5) K4(-4.5,-1.5) K5(-3.5,-1.5) K6(-2.5,-1.5) K7(-1.5,-1.5) K8(-0.5,-1.5) K9(0.5,-1.5) K10(1.5,-1.5) K11(2.5,-1.5) K12(3.5,-1.5) K13(4.5,-1.5) K14(5.5,-1.5) K15(6.5,-1.5) K16(7.5,-1.5) L1(-7.5,-2.5) L2(-6.5,-2.5) L3(-5.5,-2.5) L4(-4.5,-2.5) L5(-3.5,-2.5) L6(-2.5,-2.5) L7(-1.5,-2.5) L8(-0.5,-2.5) L9(0.5,-2.5) L10(1.5,-2.5) L11(2.5,-2.5) L12(3.5,-2.5) L13(4.5,-2.5) L14(5.5,-2.5) L15(6.5,-2.5) L16(7.5,-2.5) M1(-7.5,-3.5) M2(-6.5,-3.5) M3(-5.5,-3.5) M4(-4.5,-3.5) M5(-3.5,-3.5) M6(-2.5,-3.5) M7(-1.5,-3.5) M8(-0.5,-3.5) M9(0.5,-3.5) M10(1.5,-3.5) M11(2.5,-3.5) M12(3.5,-3.5) M13(4.5,-3.5) M14(5.5,-3.5) M15(6.5,-3.5) M16(7.5,-3.5) N1(-7.5,-4.5) N2(-6.5,-4.5) N3(-5.5,-4.5) N4(-4.5,-4.5) N5(-3.5,-4.5) N6(-2.5,-4.5) N7(-1.5,-4.5) N8(-0.5,-4.5) N9(0.5,-4.5) N10(1.5,-4.5) N11(2.5,-4.5) N12(3.5,-4.5) N13(4.5,-4.5) N14(5.5,-4.5) N15(6.5,-4.5) N16(7.5,-4.5) P1(-7.5,-5.5) P2(-6.5,-5.5) P3(-5.5,-5.5) P4(-4.5,-5.5) P5(-3.5,-5.5) P6(-2.5,-5.5) P7(-1.5,-5.5) P8(-0.5,-5.5) P9(0.5,-5.5) P10(1.5,-5.5) P11(2.5,-5.5) P12(3.5,-5.5) P13(4.5,-5.5) P14(5.5,-5.5) P15(6.5,-5.5) P16(7.5,-5.5) R1(-7.5,-6.5) R2(-6.5,-6.5) R3(-5.5,-6.5) R4(-4.5,-6.5) R5(-3.5,-6.5) R6(-2.5,-6.5) R7(-1.5,-6.5) R8(-0.5,-6.5) R9(0.5,-6.5) R10(1.5,-6.5) R11(2.5,-6.5) R12(3.5,-6.5) R13(4.5,-6.5) R14(5.5,-6.5) R15(6.5,-6.5) R16(7.5,-6.5) T1(-7.5,-7.5) T2(-6.5,-7.5) T3(-5.5,-7.5) T4(-4.5,-7.5) T5(-3.5,-7.5) T6(-2.5,-7.5) T7(-1.5,-7.5) T8(-0.5,-7.5) T9(0.5,-7.5) T10(1.5,-7.5) T11(2.5,-7.5) T12(3.5,-7.5) T13(4.5,-7.5) T14(5.5,-7.5) T15(6.5,-7.5) T16(7.5,-7.5)
Top Overlay:
  circle w0.25: c-9.15,7.5 r0.125
  region: -7.5,8.5 -8.5,7.5 -8.5,8.5
  lines w0.2: -8.5,7.5 -7.5,8.5 ; -8.5,-8.5 -8.5,8.5 8.5,8.5 8.5,-8.5 -8.5,-8.5
Mechanical 13:
  lines w0.1: -8.5,-8.5 -8.5,8.5 8.5,8.5 8.5,-8.5 -8.5,-8.5
Mechanical 15:
  lines w0.1: -0.5,0 0.5,0 ; 0,-0.5 0,0.5 ; -9.5,-9.5 -9.5,9.5 9.5,9.5 9.5,-9.5 -9.5,-9.5
3D body: height 2, standoff 0, extent -8.5,-8.5 8.5,8.5

## FG320 [mm] "320-Ball Fine Pitch Ball Grid Array (FG320)"
height 2
pads (320):
  round 0.5 smd: A1(-8.5,8.5) A2(-7.5,8.5) A3(-6.5,8.5) A4(-5.5,8.5) A5(-4.5,8.5) A6(-3.5,8.5) A7(-2.5,8.5) A8(-1.5,8.5) A9(-0.5,8.5) A10(0.5,8.5) A11(1.5,8.5) A12(2.5,8.5) A13(3.5,8.5) A14(4.5,8.5) A15(5.5,8.5) A16(6.5,8.5) A17(7.5,8.5) A18(8.5,8.5) B1(-8.5,7.5) B2(-7.5,7.5) B3(-6.5,7.5) B4(-5.5,7.5) B5(-4.5,7.5) B6(-3.5,7.5) B7(-2.5,7.5) B8(-1.5,7.5) B9(-0.5,7.5) B10(0.5,7.5) B11(1.5,7.5) B12(2.5,7.5) B13(3.5,7.5) B14(4.5,7.5) B15(5.5,7.5) B16(6.5,7.5) B17(7.5,7.5) B18(8.5,7.5) C1(-8.5,6.5) C2(-7.5,6.5) C3(-6.5,6.5) C4(-5.5,6.5) C5(-4.5,6.5) C6(-3.5,6.5) C7(-2.5,6.5) C8(-1.5,6.5) C9(-0.5,6.5) C10(0.5,6.5) C11(1.5,6.5) C12(2.5,6.5) C13(3.5,6.5) C14(4.5,6.5) C15(5.5,6.5) C16(6.5,6.5) C17(7.5,6.5) C18(8.5,6.5) D1(-8.5,5.5) D2(-7.5,5.5) D3(-6.5,5.5) D4(-5.5,5.5) D5(-4.5,5.5) D6(-3.5,5.5) D7(-2.5,5.5) D8(-1.5,5.5) D9(-0.5,5.5) D10(0.5,5.5) D11(1.5,5.5) D12(2.5,5.5) D13(3.5,5.5) D14(4.5,5.5) D15(5.5,5.5) D16(6.5,5.5) D17(7.5,5.5) D18(8.5,5.5) E1(-8.5,4.5) E2(-7.5,4.5) E3(-6.5,4.5) E4(-5.5,4.5) E5(-4.5,4.5) E6(-3.5,4.5) E7(-2.5,4.5) E8(-1.5,4.5) E9(-0.5,4.5) E10(0.5,4.5) E11(1.5,4.5) E12(2.5,4.5) E13(3.5,4.5) E14(4.5,4.5) E15(5.5,4.5) E16(6.5,4.5) E17(7.5,4.5) E18(8.5,4.5) F1(-8.5,3.5) F2(-7.5,3.5) F3(-6.5,3.5) F4(-5.5,3.5) F5(-4.5,3.5) F6(-3.5,3.5) F7(-2.5,3.5) F8(-1.5,3.5) F9(-0.5,3.5) F10(0.5,3.5) F11(1.5,3.5) F12(2.5,3.5) F13(3.5,3.5) F14(4.5,3.5) F15(5.5,3.5) F16(6.5,3.5) F17(7.5,3.5) F18(8.5,3.5) G1(-8.5,2.5) G2(-7.5,2.5) G3(-6.5,2.5) G4(-5.5,2.5) G5(-4.5,2.5) G6(-3.5,2.5) G7(-2.5,2.5) G8(-1.5,2.5) G9(-0.5,2.5) G10(0.5,2.5) G11(1.5,2.5) G12(2.5,2.5) G13(3.5,2.5) G14(4.5,2.5) G15(5.5,2.5) G16(6.5,2.5) G17(7.5,2.5) G18(8.5,2.5) H1(-8.5,1.5) H2(-7.5,1.5) H3(-6.5,1.5) H4(-5.5,1.5) H5(-4.5,1.5) H6(-3.5,1.5) H7(-2.5,1.5) H8(-1.5,1.5) H9(-0.5,1.5) H10(0.5,1.5) H11(1.5,1.5) H12(2.5,1.5) H13(3.5,1.5) H14(4.5,1.5) H15(5.5,1.5) H16(6.5,1.5) H17(7.5,1.5) H18(8.5,1.5) J1(-8.5,0.5) J2(-7.5,0.5) J3(-6.5,0.5) J4(-5.5,0.5) J5(-4.5,0.5) J6(-3.5,0.5) J7(-2.5,0.5) J8(-1.5,0.5) J11(1.5,0.5) J12(2.5,0.5) J13(3.5,0.5) J14(4.5,0.5) J15(5.5,0.5) J16(6.5,0.5) J17(7.5,0.5) J18(8.5,0.5) K1(-8.5,-0.5) K2(-7.5,-0.5) K3(-6.5,-0.5) K4(-5.5,-0.5) K5(-4.5,-0.5) K6(-3.5,-0.5) K7(-2.5,-0.5) K8(-1.5,-0.5) K11(1.5,-0.5) K12(2.5,-0.5) K13(3.5,-0.5) K14(4.5,-0.5) K15(5.5,-0.5) K16(6.5,-0.5) K17(7.5,-0.5) K18(8.5,-0.5) L1(-8.5,-1.5) L2(-7.5,-1.5) L3(-6.5,-1.5) L4(-5.5,-1.5) L5(-4.5,-1.5) L6(-3.5,-1.5) L7(-2.5,-1.5) L8(-1.5,-1.5) L9(-0.5,-1.5) L10(0.5,-1.5) L11(1.5,-1.5) L12(2.5,-1.5) L13(3.5,-1.5) L14(4.5,-1.5) L15(5.5,-1.5) L16(6.5,-1.5) L17(7.5,-1.5) L18(8.5,-1.5) M1(-8.5,-2.5) M2(-7.5,-2.5) M3(-6.5,-2.5) M4(-5.5,-2.5) M5(-4.5,-2.5) M6(-3.5,-2.5) M7(-2.5,-2.5) M8(-1.5,-2.5) M9(-0.5,-2.5) M10(0.5,-2.5) M11(1.5,-2.5) M12(2.5,-2.5) M13(3.5,-2.5) M14(4.5,-2.5) M15(5.5,-2.5) M16(6.5,-2.5) M17(7.5,-2.5) M18(8.5,-2.5) N1(-8.5,-3.5) N2(-7.5,-3.5) N3(-6.5,-3.5) N4(-5.5,-3.5) N5(-4.5,-3.5) N6(-3.5,-3.5) N7(-2.5,-3.5) N8(-1.5,-3.5) N9(-0.5,-3.5) N10(0.5,-3.5) N11(1.5,-3.5) N12(2.5,-3.5) N13(3.5,-3.5) N14(4.5,-3.5) N15(5.5,-3.5) N16(6.5,-3.5) N17(7.5,-3.5) N18(8.5,-3.5) P1(-8.5,-4.5) P2(-7.5,-4.5) P3(-6.5,-4.5) P4(-5.5,-4.5) P5(-4.5,-4.5) P6(-3.5,-4.5) P7(-2.5,-4.5) P8(-1.5,-4.5) P9(-0.5,-4.5) P10(0.5,-4.5) P11(1.5,-4.5) P12(2.5,-4.5) P13(3.5,-4.5) P14(4.5,-4.5) P15(5.5,-4.5) P16(6.5,-4.5) P17(7.5,-4.5) P18(8.5,-4.5) R1(-8.5,-5.5) R2(-7.5,-5.5) R3(-6.5,-5.5) R4(-5.5,-5.5) R5(-4.5,-5.5) R6(-3.5,-5.5) R7(-2.5,-5.5) R8(-1.5,-5.5) R9(-0.5,-5.5) R10(0.5,-5.5) R11(1.5,-5.5) R12(2.5,-5.5) R13(3.5,-5.5) R14(4.5,-5.5) R15(5.5,-5.5) R16(6.5,-5.5) R17(7.5,-5.5) R18(8.5,-5.5) T1(-8.5,-6.5) T2(-7.5,-6.5) T3(-6.5,-6.5) T4(-5.5,-6.5) T5(-4.5,-6.5) T6(-3.5,-6.5) T7(-2.5,-6.5) T8(-1.5,-6.5) T9(-0.5,-6.5) T10(0.5,-6.5) T11(1.5,-6.5) T12(2.5,-6.5) T13(3.5,-6.5) T14(4.5,-6.5) T15(5.5,-6.5) T16(6.5,-6.5) T17(7.5,-6.5) T18(8.5,-6.5) U1(-8.5,-7.5) U2(-7.5,-7.5) U3(-6.5,-7.5) U4(-5.5,-7.5) U5(-4.5,-7.5) U6(-3.5,-7.5) U7(-2.5,-7.5) U8(-1.5,-7.5) U9(-0.5,-7.5) U10(0.5,-7.5) U11(1.5,-7.5) U12(2.5,-7.5) U13(3.5,-7.5) U14(4.5,-7.5) U15(5.5,-7.5) U16(6.5,-7.5) U17(7.5,-7.5) U18(8.5,-7.5) V1(-8.5,-8.5) V2(-7.5,-8.5) V3(-6.5,-8.5) V4(-5.5,-8.5) V5(-4.5,-8.5) V6(-3.5,-8.5) V7(-2.5,-8.5) V8(-1.5,-8.5) V9(-0.5,-8.5) V10(0.5,-8.5) V11(1.5,-8.5) V12(2.5,-8.5) V13(3.5,-8.5) V14(4.5,-8.5) V15(5.5,-8.5) V16(6.5,-8.5) V17(7.5,-8.5) V18(8.5,-8.5)
Top Overlay:
  circle w0.25: c-10.15,8.5 r0.125
  region: -8.5,9.5 -9.5,8.5 -9.5,9.5
  lines w0.2: -9.5,8.5 -8.5,9.5 ; -9.5,-9.5 9.5,-9.5 9.5,9.5 -9.5,9.5 -9.5,-9.5
Mechanical 13:
  lines w0.1: -9.5,-9.5 9.5,-9.5 9.5,9.5 -9.5,9.5 -9.5,-9.5
Mechanical 15:
  lines w0.1: -0.5,0 0.5,0 ; 0,-0.5 0,0.5 ; -10.5,-10.5 10.5,-10.5 10.5,10.5 -10.5,10.5 -10.5,-10.5
3D body: height 2, standoff 0, extent -9.5,-9.5 9.5,9.5

## FG324 [mm] "324-Ball Fine Pitch Ball Grid Array 1.00 mm Pitch (FG324)"
height 2.5
pads (324):
  round 0.5 smd: A1(-10.5,10.5) A2(-9.5,10.5) A3(-8.5,10.5) A4(-7.5,10.5) A5(-6.5,10.5) A6(-5.5,10.5) A7(-4.5,10.5) A8(-3.5,10.5) A9(-2.5,10.5) A10(-1.5,10.5) A11(-0.5,10.5) A12(0.5,10.5) A13(1.5,10.5) A14(2.5,10.5) A15(3.5,10.5) A16(4.5,10.5) A17(5.5,10.5) A18(6.5,10.5) A19(7.5,10.5) A20(8.5,10.5) A21(9.5,10.5) A22(10.5,10.5) AA1(-10.5,-9.5) AA2(-9.5,-9.5) AA3(-8.5,-9.5) AA4(-7.5,-9.5) AA5(-6.5,-9.5) AA6(-5.5,-9.5) AA7(-4.5,-9.5) AA8(-3.5,-9.5) AA9(-2.5,-9.5) AA10(-1.5,-9.5) AA11(-0.5,-9.5) AA12(0.5,-9.5) AA13(1.5,-9.5) AA14(2.5,-9.5) AA15(3.5,-9.5) AA16(4.5,-9.5) AA17(5.5,-9.5) AA18(6.5,-9.5) AA19(7.5,-9.5) AA20(8.5,-9.5) AA21(9.5,-9.5) AA22(10.5,-9.5) AB1(-10.5,-10.5) AB2(-9.5,-10.5) AB3(-8.5,-10.5) AB4(-7.5,-10.5) AB5(-6.5,-10.5) AB6(-5.5,-10.5) AB7(-4.5,-10.5) AB8(-3.5,-10.5) AB9(-2.5,-10.5) AB10(-1.5,-10.5) AB11(-0.5,-10.5) AB12(0.5,-10.5) AB13(1.5,-10.5) AB14(2.5,-10.5) AB15(3.5,-10.5) AB16(4.5,-10.5) AB17(5.5,-10.5) AB18(6.5,-10.5) AB19(7.5,-10.5) AB20(8.5,-10.5) AB21(9.5,-10.5) AB22(10.5,-10.5) B1(-10.5,9.5) B2(-9.5,9.5) B3(-8.5,9.5) B4(-7.5,9.5) B5(-6.5,9.5) B6(-5.5,9.5) B7(-4.5,9.5) B8(-3.5,9.5) B9(-2.5,9.5) B10(-1.5,9.5) B11(-0.5,9.5) B12(0.5,9.5) B13(1.5,9.5) B14(2.5,9.5) B15(3.5,9.5) B16(4.5,9.5) B17(5.5,9.5) B18(6.5,9.5) B19(7.5,9.5) B20(8.5,9.5) B21(9.5,9.5) B22(10.5,9.5) C1(-10.5,8.5) C2(-9.5,8.5) C3(-8.5,8.5) C4(-7.5,8.5) C5(-6.5,8.5) C6(-5.5,8.5) C7(-4.5,8.5) C8(-3.5,8.5) C9(-2.5,8.5) C10(-1.5,8.5) C11(-0.5,8.5) C12(0.5,8.5) C13(1.5,8.5) C14(2.5,8.5) C15(3.5,8.5) C16(4.5,8.5) C17(5.5,8.5) C18(6.5,8.5) C19(7.5,8.5) C20(8.5,8.5) C21(9.5,8.5) C22(10.5,8.5) D1(-10.5,7.5) D2(-9.5,7.5) D3(-8.5,7.5) D4(-7.5,7.5) D5(-6.5,7.5) D6(-5.5,7.5) D7(-4.5,7.5) D8(-3.5,7.5) D9(-2.5,7.5) D10(-1.5,7.5) D11(-0.5,7.5) D12(0.5,7.5) D13(1.5,7.5) D14(2.5,7.5) D15(3.5,7.5) D16(4.5,7.5) D17(5.5,7.5) D18(6.5,7.5) D19(7.5,7.5) D20(8.5,7.5) D21(9.5,7.5) D22(10.5,7.5) E1(-10.5,6.5) E2(-9.5,6.5) E3(-8.5,6.5) E4(-7.5,6.5) E19(7.5,6.5) E20(8.5,6.5) E21(9.5,6.5) E22(10.5,6.5) F1(-10.5,5.5) F2(-9.5,5.5) F3(-8.5,5.5) F4(-7.5,5.5) F19(7.5,5.5) F20(8.5,5.5) F21(9.5,5.5) F22(10.5,5.5) G1(-10.5,4.5) G2(-9.5,4.5) G3(-8.5,4.5) G4(-7.5,4.5) G19(7.5,4.5) G20(8.5,4.5) G21(9.5,4.5) G22(10.5,4.5) H1(-10.5,3.5) H2(-9.5,3.5) H3(-8.5,3.5) H4(-7.5,3.5) H19(7.5,3.5) H20(8.5,3.5) H21(9.5,3.5) H22(10.5,3.5) J1(-10.5,2.5) J2(-9.5,2.5) J3(-8.5,2.5) J4(-7.5,2.5) J9(-2.5,2.5) J10(-1.5,2.5) J11(-0.5,2.5) J12(0.5,2.5) J13(1.5,2.5) J14(2.5,2.5) J19(7.5,2.5) J20(8.5,2.5) J21(9.5,2.5) J22(10.5,2.5) K1(-10.5,1.5) K2(-9.5,1.5) K3(-8.5,1.5) K4(-7.5,1.5) K9(-2.5,1.5) K10(-1.5,1.5) K11(-0.5,1.5) K12(0.5,1.5) K13(1.5,1.5) K14(2.5,1.5) K19(7.5,1.5) K20(8.5,1.5) K21(9.5,1.5) K22(10.5,1.5) L1(-10.5,0.5) L2(-9.5,0.5) L3(-8.5,0.5) L4(-7.5,0.5) L9(-2.5,0.5) L10(-1.5,0.5) L11(-0.5,0.5) L12(0.5,0.5) L13(1.5,0.5) L14(2.5,0.5) L19(7.5,0.5) L20(8.5,0.5) L21(9.5,0.5) L22(10.5,0.5) M1(-10.5,-0.5) M2(-9.5,-0.5) M3(-8.5,-0.5) M4(-7.5,-0.5) M9(-2.5,-0.5) M10(-1.5,-0.5) M11(-0.5,-0.5) M12(0.5,-0.5) M13(1.5,-0.5) M14(2.5,-0.5) M19(7.5,-0.5) M20(8.5,-0.5) M21(9.5,-0.5) M22(10.5,-0.5) N1(-10.5,-1.5) N2(-9.5,-1.5) N3(-8.5,-1.5) N4(-7.5,-1.5) N9(-2.5,-1.5) N10(-1.5,-1.5) N11(-0.5,-1.5) N12(0.5,-1.5) N13(1.5,-1.5) N14(2.5,-1.5) N19(7.5,-1.5) N20(8.5,-1.5) N21(9.5,-1.5) N22(10.5,-1.5) P1(-10.5,-2.5) P2(-9.5,-2.5) P3(-8.5,-2.5) P4(-7.5,-2.5) P9(-2.5,-2.5) P10(-1.5,-2.5) P11(-0.5,-2.5) P12(0.5,-2.5) P13(1.5,-2.5) P14(2.5,-2.5) P19(7.5,-2.5) P20(8.5,-2.5) P21(9.5,-2.5) P22(10.5,-2.5) R1(-10.5,-3.5) R2(-9.5,-3.5) R3(-8.5,-3.5) R4(-7.5,-3.5) R19(7.5,-3.5) R20(8.5,-3.5) R21(9.5,-3.5) R22(10.5,-3.5) T1(-10.5,-4.5) T2(-9.5,-4.5) T3(-8.5,-4.5) T4(-7.5,-4.5) T19(7.5,-4.5) T20(8.5,-4.5) T21(9.5,-4.5) T22(10.5,-4.5) U1(-10.5,-5.5) U2(-9.5,-5.5) U3(-8.5,-5.5) U4(-7.5,-5.5) U19(7.5,-5.5) U20(8.5,-5.5) U21(9.5,-5.5) U22(10.5,-5.5) V1(-10.5,-6.5) V2(-9.5,-6.5) V3(-8.5,-6.5) V4(-7.5,-6.5) V19(7.5,-6.5) V20(8.5,-6.5) V21(9.5,-6.5) V22(10.5,-6.5) W1(-10.5,-7.5) W2(-9.5,-7.5) W3(-8.5,-7.5) W4(-7.5,-7.5) W5(-6.5,-7.5) W6(-5.5,-7.5) W7(-4.5,-7.5) W8(-3.5,-7.5) W9(-2.5,-7.5) W10(-1.5,-7.5) W11(-0.5,-7.5) W12(0.5,-7.5) W13(1.5,-7.5) W14(2.5,-7.5) W15(3.5,-7.5) W16(4.5,-7.5) W17(5.5,-7.5) W18(6.5,-7.5) W19(7.5,-7.5) W20(8.5,-7.5) W21(9.5,-7.5) W22(10.5,-7.5) Y1(-10.5,-8.5) Y2(-9.5,-8.5) Y3(-8.5,-8.5) Y4(-7.5,-8.5) Y5(-6.5,-8.5) Y6(-5.5,-8.5) Y7(-4.5,-8.5) Y8(-3.5,-8.5) Y9(-2.5,-8.5) Y10(-1.5,-8.5) Y11(-0.5,-8.5) Y12(0.5,-8.5) Y13(1.5,-8.5) Y14(2.5,-8.5) Y15(3.5,-8.5) Y16(4.5,-8.5) Y17(5.5,-8.5) Y18(6.5,-8.5) Y19(7.5,-8.5) Y20(8.5,-8.5) Y21(9.5,-8.5) Y22(10.5,-8.5)
Top Overlay:
  circle w0.25: c-12.15,10.5 r0.125
  region: -10.5,11.5 -11.5,10.5 -11.5,11.5
  lines w0.2: -11.5,10.5 -10.5,11.5 ; -11.5,-11.5 11.5,-11.5 11.5,11.5 -11.5,11.5 -11.5,-11.5
Mechanical 13:
  lines w0.1: -11.5,-11.5 11.5,-11.5 11.5,11.5 -11.5,11.5 -11.5,-11.5
Mechanical 15:
  lines w0.1: -0.5,0 0.5,0 ; 0,-0.5 0,0.5 ; -12.5,-12.5 12.5,-12.5 12.5,12.5 -12.5,12.5 -12.5,-12.5
3D body: height 2.5, standoff 0, extent -11.5,-11.5 11.5,11.5

## FG400 [mm] "400-Ball Fine Pitch Ball Grid Array 1.00 mm Pitch (FG400)"
height 2.43
pads (400):
  round 0.5 smd: A1(-9.5,9.5) A2(-8.5,9.5) A3(-7.5,9.5) A4(-6.5,9.5) A5(-5.5,9.5) A6(-4.5,9.5) A7(-3.5,9.5) A8(-2.5,9.5) A9(-1.5,9.5) A10(-0.5,9.5) A11(0.5,9.5) A12(1.5,9.5) A13(2.5,9.5) A14(3.5,9.5) A15(4.5,9.5) A16(5.5,9.5) A17(6.5,9.5) A18(7.5,9.5) A19(8.5,9.5) A20(9.5,9.5) B1(-9.5,8.5) B2(-8.5,8.5) B3(-7.5,8.5) B4(-6.5,8.5) B5(-5.5,8.5) B6(-4.5,8.5) B7(-3.5,8.5) B8(-2.5,8.5) B9(-1.5,8.5) B10(-0.5,8.5) B11(0.5,8.5) B12(1.5,8.5) B13(2.5,8.5) B14(3.5,8.5) B15(4.5,8.5) B16(5.5,8.5) B17(6.5,8.5) B18(7.5,8.5) B19(8.5,8.5) B20(9.5,8.5) C1(-9.5,7.5) C2(-8.5,7.5) C3(-7.5,7.5) C4(-6.5,7.5) C5(-5.5,7.5) C6(-4.5,7.5) C7(-3.5,7.5) C8(-2.5,7.5) C9(-1.5,7.5) C10(-0.5,7.5) C11(0.5,7.5) C12(1.5,7.5) C13(2.5,7.5) C14(3.5,7.5) C15(4.5,7.5) C16(5.5,7.5) C17(6.5,7.5) C18(7.5,7.5) C19(8.5,7.5) C20(9.5,7.5) D1(-9.5,6.5) D2(-8.5,6.5) D3(-7.5,6.5) D4(-6.5,6.5) D5(-5.5,6.5) D6(-4.5,6.5) D7(-3.5,6.5) D8(-2.5,6.5) D9(-1.5,6.5) D10(-0.5,6.5) D11(0.5,6.5) D12(1.5,6.5) D13(2.5,6.5) D14(3.5,6.5) D15(4.5,6.5) D16(5.5,6.5) D17(6.5,6.5) D18(7.5,6.5) D19(8.5,6.5) D20(9.5,6.5) E1(-9.5,5.5) E2(-8.5,5.5) E3(-7.5,5.5) E4(-6.5,5.5) E5(-5.5,5.5) E6(-4.5,5.5) E7(-3.5,5.5) E8(-2.5,5.5) E9(-1.5,5.5) E10(-0.5,5.5) E11(0.5,5.5) E12(1.5,5.5) E13(2.5,5.5) E14(3.5,5.5) E15(4.5,5.5) E16(5.5,5.5) E17(6.5,5.5) E18(7.5,5.5) E19(8.5,5.5) E20(9.5,5.5) F1(-9.5,4.5) F2(-8.5,4.5) F3(-7.5,4.5) F4(-6.5,4.5) F5(-5.5,4.5) F6(-4.5,4.5) F7(-3.5,4.5) F8(-2.5,4.5) F9(-1.5,4.5) F10(-0.5,4.5) F11(0.5,4.5) F12(1.5,4.5) F13(2.5,4.5) F14(3.5,4.5) F15(4.5,4.5) F16(5.5,4.5) F17(6.5,4.5) F18(7.5,4.5) F19(8.5,4.5) F20(9.5,4.5) G1(-9.5,3.5) G2(-8.5,3.5) G3(-7.5,3.5) G4(-6.5,3.5) G5(-5.5,3.5) G6(-4.5,3.5) G7(-3.5,3.5) G8(-2.5,3.5) G9(-1.5,3.5) G10(-0.5,3.5) G11(0.5,3.5) G12(1.5,3.5) G13(2.5,3.5) G14(3.5,3.5) G15(4.5,3.5) G16(5.5,3.5) G17(6.5,3.5) G18(7.5,3.5) G19(8.5,3.5) G20(9.5,3.5) H1(-9.5,2.5) H2(-8.5,2.5) H3(-7.5,2.5) H4(-6.5,2.5) H5(-5.5,2.5) H6(-4.5,2.5) H7(-3.5,2.5) H8(-2.5,2.5) H9(-1.5,2.5) H10(-0.5,2.5) H11(0.5,2.5) H12(1.5,2.5) H13(2.5,2.5) H14(3.5,2.5) H15(4.5,2.5) H16(5.5,2.5) H17(6.5,2.5) H18(7.5,2.5) H19(8.5,2.5) H20(9.5,2.5) J1(-9.5,1.5) J2(-8.5,1.5) J3(-7.5,1.5) J4(-6.5,1.5) J5(-5.5,1.5) J6(-4.5,1.5) J7(-3.5,1.5) J8(-2.5,1.5) J9(-1.5,1.5) J10(-0.5,1.5) J11(0.5,1.5) J12(1.5,1.5) J13(2.5,1.5) J14(3.5,1.5) J15(4.5,1.5) J16(5.5,1.5) J17(6.5,1.5) J18(7.5,1.5) J19(8.5,1.5) J20(9.5,1.5) K1(-9.5,0.5) K2(-8.5,0.5) K3(-7.5,0.5) K4(-6.5,0.5) K5(-5.5,0.5) K6(-4.5,0.5) K7(-3.5,0.5) K8(-2.5,0.5) K9(-1.5,0.5) K10(-0.5,0.5) K11(0.5,0.5) K12(1.5,0.5) K13(2.5,0.5) K14(3.5,0.5) K15(4.5,0.5) K16(5.5,0.5) K17(6.5,0.5) K18(7.5,0.5) K19(8.5,0.5) K20(9.5,0.5) L1(-9.5,-0.5) L2(-8.5,-0.5) L3(-7.5,-0.5) L4(-6.5,-0.5) L5(-5.5,-0.5) L6(-4.5,-0.5) L7(-3.5,-0.5) L8(-2.5,-0.5) L9(-1.5,-0.5) L10(-0.5,-0.5) L11(0.5,-0.5) L12(1.5,-0.5) L13(2.5,-0.5) L14(3.5,-0.5) L15(4.5,-0.5) L16(5.5,-0.5) L17(6.5,-0.5) L18(7.5,-0.5) L19(8.5,-0.5) L20(9.5,-0.5) M1(-9.5,-1.5) M2(-8.5,-1.5) M3(-7.5,-1.5) M4(-6.5,-1.5) M5(-5.5,-1.5) M6(-4.5,-1.5) M7(-3.5,-1.5) M8(-2.5,-1.5) M9(-1.5,-1.5) M10(-0.5,-1.5) M11(0.5,-1.5) M12(1.5,-1.5) M13(2.5,-1.5) M14(3.5,-1.5) M15(4.5,-1.5) M16(5.5,-1.5) M17(6.5,-1.5) M18(7.5,-1.5) M19(8.5,-1.5) M20(9.5,-1.5) N1(-9.5,-2.5) N2(-8.5,-2.5) N3(-7.5,-2.5) N4(-6.5,-2.5) N5(-5.5,-2.5) N6(-4.5,-2.5) N7(-3.5,-2.5) N8(-2.5,-2.5) N9(-1.5,-2.5) N10(-0.5,-2.5) N11(0.5,-2.5) N12(1.5,-2.5) N13(2.5,-2.5) N14(3.5,-2.5) N15(4.5,-2.5) N16(5.5,-2.5) N17(6.5,-2.5) N18(7.5,-2.5) N19(8.5,-2.5) N20(9.5,-2.5) P1(-9.5,-3.5) P2(-8.5,-3.5) P3(-7.5,-3.5) P4(-6.5,-3.5) P5(-5.5,-3.5) P6(-4.5,-3.5) P7(-3.5,-3.5) P8(-2.5,-3.5) P9(-1.5,-3.5) P10(-0.5,-3.5) P11(0.5,-3.5) P12(1.5,-3.5) P13(2.5,-3.5) P14(3.5,-3.5) P15(4.5,-3.5) P16(5.5,-3.5) P17(6.5,-3.5) P18(7.5,-3.5) P19(8.5,-3.5) P20(9.5,-3.5) R1(-9.5,-4.5) R2(-8.5,-4.5) R3(-7.5,-4.5) R4(-6.5,-4.5) R5(-5.5,-4.5) R6(-4.5,-4.5) R7(-3.5,-4.5) R8(-2.5,-4.5) R9(-1.5,-4.5) R10(-0.5,-4.5) R11(0.5,-4.5) R12(1.5,-4.5) R13(2.5,-4.5) R14(3.5,-4.5) R15(4.5,-4.5) R16(5.5,-4.5) R17(6.5,-4.5) R18(7.5,-4.5) R19(8.5,-4.5) R20(9.5,-4.5) T1(-9.5,-5.5) T2(-8.5,-5.5) T3(-7.5,-5.5) T4(-6.5,-5.5) T5(-5.5,-5.5) T6(-4.5,-5.5) T7(-3.5,-5.5) T8(-2.5,-5.5) T9(-1.5,-5.5) T10(-0.5,-5.5) T11(0.5,-5.5) T12(1.5,-5.5) T13(2.5,-5.5) T14(3.5,-5.5) T15(4.5,-5.5) T16(5.5,-5.5) T17(6.5,-5.5) T18(7.5,-5.5) T19(8.5,-5.5) T20(9.5,-5.5) U1(-9.5,-6.5) U2(-8.5,-6.5) U3(-7.5,-6.5) U4(-6.5,-6.5) U5(-5.5,-6.5) U6(-4.5,-6.5) U7(-3.5,-6.5) U8(-2.5,-6.5) U9(-1.5,-6.5) U10(-0.5,-6.5) U11(0.5,-6.5) U12(1.5,-6.5) U13(2.5,-6.5) U14(3.5,-6.5) U15(4.5,-6.5) U16(5.5,-6.5) U17(6.5,-6.5) U18(7.5,-6.5) U19(8.5,-6.5) U20(9.5,-6.5) V1(-9.5,-7.5) V2(-8.5,-7.5) V3(-7.5,-7.5) V4(-6.5,-7.5) V5(-5.5,-7.5) V6(-4.5,-7.5) V7(-3.5,-7.5) V8(-2.5,-7.5) V9(-1.5,-7.5) V10(-0.5,-7.5) V11(0.5,-7.5) V12(1.5,-7.5) V13(2.5,-7.5) V14(3.5,-7.5) V15(4.5,-7.5) V16(5.5,-7.5) V17(6.5,-7.5) V18(7.5,-7.5) V19(8.5,-7.5) V20(9.5,-7.5) W1(-9.5,-8.5) W2(-8.5,-8.5) W3(-7.5,-8.5) W4(-6.5,-8.5) W5(-5.5,-8.5) W6(-4.5,-8.5) W7(-3.5,-8.5) W8(-2.5,-8.5) W9(-1.5,-8.5) W10(-0.5,-8.5) W11(0.5,-8.5) W12(1.5,-8.5) W13(2.5,-8.5) W14(3.5,-8.5) W15(4.5,-8.5) W16(5.5,-8.5) W17(6.5,-8.5) W18(7.5,-8.5) W19(8.5,-8.5) W20(9.5,-8.5) Y1(-9.5,-9.5) Y2(-8.5,-9.5) Y3(-7.5,-9.5) Y4(-6.5,-9.5) Y5(-5.5,-9.5) Y6(-4.5,-9.5) Y7(-3.5,-9.5) Y8(-2.5,-9.5) Y9(-1.5,-9.5) Y10(-0.5,-9.5) Y11(0.5,-9.5) Y12(1.5,-9.5) Y13(2.5,-9.5) Y14(3.5,-9.5) Y15(4.5,-9.5) Y16(5.5,-9.5) Y17(6.5,-9.5) Y18(7.5,-9.5) Y19(8.5,-9.5) Y20(9.5,-9.5)
Top Overlay:
  circle w0.25: c-11.15,9.5 r0.125
  region: -9.5,10.5 -10.5,9.5 -10.5,10.5
  lines w0.2: -10.5,9.5 -9.5,10.5 ; -10.5,-10.5 -10.5,10.5 10.5,10.5 10.5,-10.5 -10.5,-10.5
Mechanical 13:
  lines w0.1: -10.5,-10.5 -10.5,10.5 10.5,10.5 10.5,-10.5 -10.5,-10.5
Mechanical 15:
  lines w0.1: -0.5,0 0.5,0 ; 0,-0.5 0,0.5 ; -11.5,-11.5 -11.5,11.5 11.5,11.5 11.5,-11.5 -11.5,-11.5
3D body: height 2.43, standoff 0, extent -10.5,-10.5 10.5,10.5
